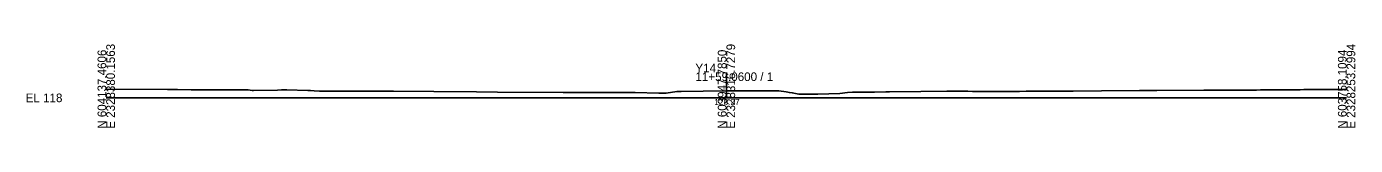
# Model space of a CAD drawing. Extents: x -26 to 2328312, y 990 to 603967.
# Drawn here: x 4174.3 to 4602.8, y 990.3 to 1017.4 of the extents above; entities that cross this region are included whole.
import ezdxf

# ---------------------------------------------------------------- set-up
doc = ezdxf.new("R2010")
doc.units = 0
for name, color, linetype in [('Exist CMT Pavement', 7, 'Continuous'), ('Exist Cross Section Cell', 7, 'Continuous'), ('Exist XS Center Line Elevation Label', 7, 'Continuous'), ('Exist XS Ground Line', 7, 'Continuous'), ('Prop XS Earthwork Shape', 7, 'Continuous')]:
    doc.layers.add(name, color=color, linetype=linetype)

msp = doc.modelspace()

# ---------------------------------------------------------------- linework, layer by layer
at = {"layer": 'Exist CMT Pavement'}
for p, q in [((4399.9, 1002.37), (4400.1, 1002.37)), ((4399.9, 1002.27), (4399.9, 1002.37)), ((4400, 1002.27), (4400, 1002.37)), ((4400.1, 1002.37), (4400.1, 1002.27))]:
    msp.add_line(p, q, dxfattribs=at)
at = {"layer": 'Exist Cross Section Cell'}
for p, q in [((4400, 1000), (4400, 1008.25)), ((4200, 1000), (4400, 1000)), ((4400, 1000), (4600, 1000))]:
    msp.add_line(p, q, dxfattribs=at)
at = {"layer": 'Exist XS Ground Line'}
msp.add_lwpolyline([(4200, 1002.83), (4219.7, 1002.7), (4222.94, 1002.68), (4227.41, 1002.65), (4245.75, 1002.57), (4247.07, 1002.37), (4247.52, 1002.37), (4255.25, 1002.53), (4256.52, 1002.58), (4257.49, 1002.6), (4258.2, 1002.58), (4265.03, 1002.39), (4265.83, 1002.36), (4267.02, 1002.23), (4268.8, 1002.16), (4283.4, 1002.2), (4284.53, 1002.17), (4292.6, 1002.16), (4305.6, 1002.03), (4319.38, 1001.9), (4326.12, 1001.84), (4347.32, 1001.76), (4364.8, 1001.73), (4370.62, 1001.7), (4378.19, 1001.55), (4378.71, 1001.55), (4380.53, 1001.53), (4383.98, 1002.03), (4385.36, 1002.03), (4392.51, 1002.2), (4400, 1002.27), (4405.17, 1002.32), (4407.61, 1002.3), (4416.92, 1002.26), (4419.3, 1001.93), (4420.3, 1001.7), (4421.23, 1001.65), (4423.4, 1001.16), (4429.43, 1001.24), (4436.54, 1001.41), (4439.04, 1001.73), (4440.7, 1001.84), (4443, 1001.88), (4444.26, 1001.84), (4447.73, 1001.86), (4451.45, 1001.9), (4452.62, 1001.91), (4462.7, 1002.04), (4471.03, 1002.16), (4474.37, 1002.18), (4477.12, 1002.14), (4477.85, 1002.13), (4479.32, 1002.09), (4481.82, 1002.02), (4482.42, 1002.03), (4484.56, 1002.06), (4485.58, 1002.05), (4486.03, 1002.06), (4487.74, 1002.06), (4490.38, 1002.08), (4492, 1002.08), (4493.11, 1002.09), (4494.55, 1002.09), (4496.67, 1002.12), (4497.38, 1002.12), (4498.88, 1002.12), (4500.06, 1002.12), (4502.76, 1002.13), (4504.38, 1002.14), (4505.47, 1002.17), (4506.25, 1002.18), (4511.84, 1002.2), (4520.9, 1002.25), (4533.25, 1002.35), (4534.25, 1002.36), (4537.47, 1002.38), (4538.85, 1002.39), (4553.91, 1002.45), (4555.33, 1002.45), (4555.64, 1002.45), (4556.47, 1002.45), (4558.18, 1002.46), (4559.34, 1002.46), (4560.73, 1002.47), (4562.77, 1002.48), (4563.27, 1002.49), (4565.4, 1002.5), (4565.92, 1002.5), (4568.36, 1002.52), (4570.02, 1002.53), (4570.91, 1002.54), (4572.21, 1002.55), (4573.45, 1002.56), (4574.3, 1002.57), (4576, 1002.59), (4578.71, 1002.61), (4580.71, 1002.62), (4581.09, 1002.63), (4581.65, 1002.63), (4583.64, 1002.64), (4584.98, 1002.64), (4586.18, 1002.66), (4587.95, 1002.67), (4588.73, 1002.67), (4589.25, 1002.68), (4591.39, 1002.7), (4592.01, 1002.7), (4593.82, 1002.72), (4595.66, 1002.72), (4596.36, 1002.73), (4597.39, 1002.73), (4598.91, 1002.74), (4600, 1002.75)], dxfattribs=at)
at = {"layer": 'Prop XS Earthwork Shape'}
for points in [[(4400, 1002.27), (4400, 1002.37), (4399.9, 1002.37), (4399.9, 1002.27)], [(4400, 1002.27), (4400, 1002.37), (4400.1, 1002.37), (4400.1, 1002.27)]]:
    msp.add_lwpolyline(points, close=True, dxfattribs=at)

# ---------------------------------------------------------------- texts
at = {"layer": 'Exist Cross Section Cell'}
for s, p in [('E 2328380.1563', (4202.8, 990)), ('E 2328316.7279', (4402.8, 990)), ('E 2328253.2994', (4602.8, 990)), ('N 604137.4606', (4200, 990)), ('N 603947.7850', (4400, 990)), ('N 603758.1094', (4600, 990))]:
    msp.add_text(s, height=2.8, rotation=90, dxfattribs=at).set_placement(p)
for s, p in [('Y14', (4390, 1008.25)), ('11+59.0600 / 1', (4390, 1005.45)), ('EL 118', (4174, 998.6))]:
    msp.add_text(s, height=2.8, dxfattribs=at).set_placement(p)
at = {"layer": 'Exist XS Center Line Elevation Label'}
msp.add_text('120.27', height=2, dxfattribs=at).set_placement((4396.08, 997.64))

doc.saveas('drawing.dxf')
